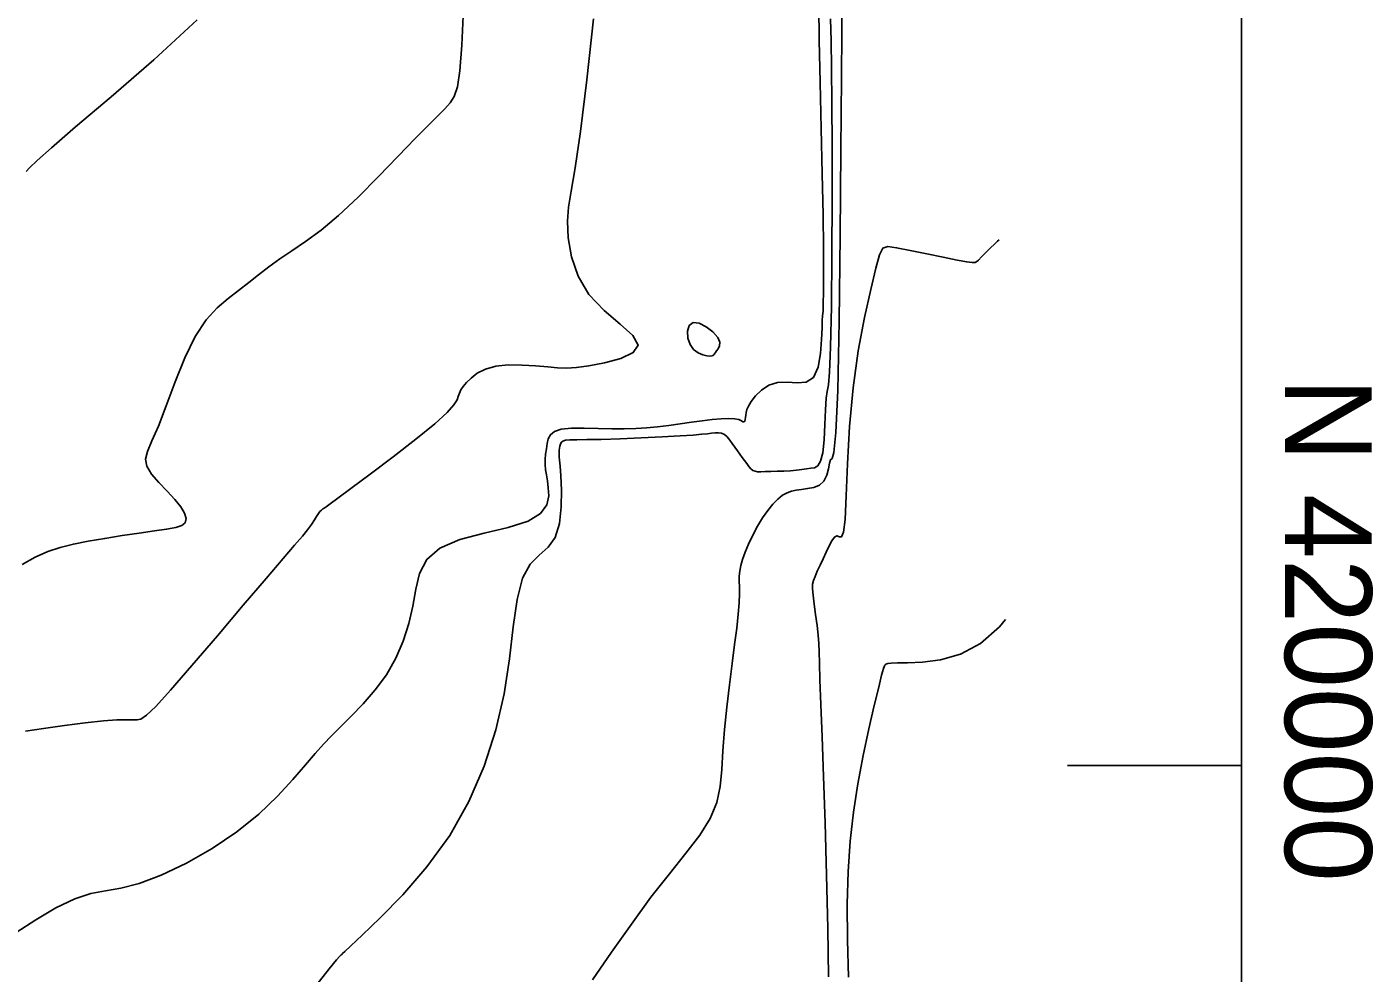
# Model space of a CAD drawing. Extents: x 2566142 to 2571431, y 418755 to 421584.
# Drawn here: x 2571198.2 to 2571430.5, y 419964.2 to 420127.5 of the extents above; entities that cross this region are included whole.
import ezdxf

# ---------------------------------------------------------------- set-up
doc = ezdxf.new("R2010")
doc.units = 0
for name, color, linetype in [('Contour_ADS_Major', 7, 'Continuous'), ('Contour_ADS_Minor', 7, 'Continuous'), ('Contour_ADS_State_Plane_Border', 7, 'Continuous')]:
    doc.layers.add(name, color=color, linetype=linetype)

msp = doc.modelspace()

# ---------------------------------------------------------------- linework, layer by layer
at = {"layer": 'Contour_ADS_Major'}
for points in [[(2571335.54, 420077.62), (2571335.6, 420078.43), (2571335.65, 420079.68), (2571335.69, 420081.8), (2571335.7, 420084.96), (2571335.68, 420089.33), (2571335.6, 420095.06), (2571335.46, 420102.13), (2571335.28, 420109.99), (2571335.1, 420117.92), (2571334.95, 420125.2), (2571334.86, 420131.28)], [(2571196.36, 419971.19), (2571199.72, 419973.37), (2571203.21, 419975.42), (2571206.47, 419977.01), (2571209.25, 419977.91), (2571211.78, 419978.4), (2571214.43, 419978.86), (2571217.56, 419979.66), (2571221.4, 419981.1), (2571225.73, 419983.14), (2571230.2, 419985.66), (2571234.46, 419988.54), (2571238.22, 419991.62), (2571241.43, 419994.72), (2571244.1, 419997.62), (2571246.27, 420000.13), (2571247.98, 420002.1), (2571249.4, 420003.69), (2571250.78, 420005.14), (2571252.32, 420006.69), (2571254.18, 420008.53), (2571256.25, 420010.66), (2571258.33, 420013.06), (2571260.25, 420015.69), (2571261.85, 420018.53), (2571263.13, 420021.5), (2571264.1, 420024.53), (2571264.79, 420027.54), (2571265.3, 420030.47), (2571265.96, 420033.18), (2571267.21, 420035.58), (2571269.45, 420037.54), (2571272.93, 420039), (2571277.11, 420040.12), (2571281.28, 420041.11), (2571284.71, 420042.19), (2571286.87, 420043.53), (2571287.94, 420045.02), (2571288.26, 420046.55), (2571288.19, 420047.96), (2571288.03, 420049.15), (2571287.86, 420050.16), (2571287.72, 420051.07), (2571287.64, 420051.95), (2571287.65, 420052.86), (2571287.72, 420053.78), (2571287.85, 420054.7), (2571288, 420055.58), (2571288.19, 420056.39), (2571288.55, 420057.1), (2571289.24, 420057.67), (2571290.42, 420058.05), (2571292.2, 420058.23), (2571294.4, 420058.25), (2571296.8, 420058.2), (2571299.16, 420058.14), (2571301.31, 420058.13), (2571303.27, 420058.17), (2571305.15, 420058.29), (2571307.03, 420058.46), (2571308.97, 420058.7), (2571310.94, 420058.98), (2571312.88, 420059.26), (2571314.74, 420059.52), (2571316.46, 420059.73), (2571318, 420059.87), (2571319.31, 420059.92), (2571320.33, 420059.87), (2571321.05, 420059.71), (2571321.51, 420059.52), (2571321.79, 420059.36), (2571321.96, 420059.31), (2571322.08, 420059.44), (2571322.17, 420059.72), (2571322.23, 420060.09), (2571322.28, 420060.51), (2571322.33, 420060.95), (2571322.45, 420061.45), (2571322.72, 420062.06), (2571323.2, 420062.84), (2571323.95, 420063.81), (2571324.98, 420064.81), (2571326.25, 420065.65), (2571327.75, 420066.13), (2571329.44, 420066.16), (2571331.15, 420066.04), (2571332.72, 420066.19), (2571333.96, 420067.01), (2571334.76, 420068.77), (2571335.18, 420071.11), (2571335.36, 420073.53), (2571335.43, 420075.55), (2571335.48, 420076.81), (2571335.54, 420077.62)]]:
    msp.add_lwpolyline(points, dxfattribs=at)
at = {"layer": 'Contour_ADS_Minor'}
for points in [[(2571273.29, 420124.34), (2571273.57, 420130.68)], [(2571318.11, 419999.33), (2571318.31, 420002.57), (2571318.62, 420006.21), (2571319.02, 420010.07), (2571319.48, 420013.95), (2571319.94, 420017.62), (2571320.35, 420020.9), (2571320.71, 420023.74), (2571320.98, 420026.14), (2571321.14, 420028.1), (2571321.2, 420029.64), (2571321.19, 420030.84), (2571321.15, 420031.82), (2571321.15, 420032.7), (2571321.23, 420033.58), (2571321.4, 420034.53), (2571321.71, 420035.59), (2571322.15, 420036.82), (2571322.76, 420038.24), (2571323.49, 420039.78), (2571324.31, 420041.33), (2571325.18, 420042.78), (2571326.06, 420044.05), (2571326.94, 420045.13), (2571327.79, 420046), (2571328.61, 420046.65), (2571329.39, 420047.1), (2571330.17, 420047.39), (2571330.99, 420047.56), (2571331.9, 420047.68), (2571332.93, 420047.8), (2571333.99, 420048), (2571334.97, 420048.4), (2571335.74, 420049.09), (2571336.24, 420050.1), (2571336.54, 420051.23), (2571336.72, 420052.22), (2571336.91, 420052.8), (2571337.17, 420053.01), (2571337.49, 420054.06), (2571337.83, 420057.47), (2571338.14, 420064.74), (2571338.38, 420076.7), (2571338.56, 420091.43), (2571338.69, 420106.3), (2571338.78, 420118.69), (2571338.83, 420126.64), (2571338.85, 420130.76)], [(2571198.07, 420102.54), (2571198.68, 420103.2), (2571199.95, 420104.43), (2571202.42, 420106.64), (2571206.6, 420110.24), (2571212.75, 420115.46), (2571220.1, 420121.84), (2571227.61, 420128.72)], [(2571291.5, 420093.96), (2571291.69, 420096.41), (2571292.13, 420099.17), (2571292.83, 420103.19), (2571293.74, 420109.43), (2571294.84, 420118.39), (2571295.99, 420128.9)], [(2571315.67, 420057.29), (2571316.37, 420057.38), (2571316.99, 420057.45), (2571317.56, 420057.46), (2571318.09, 420057.37), (2571318.59, 420057.13), (2571319.06, 420056.72), (2571319.52, 420056.19), (2571319.95, 420055.58), (2571320.39, 420054.94), (2571320.82, 420054.33), (2571321.25, 420053.74), (2571321.66, 420053.18), (2571322.06, 420052.64), (2571322.44, 420052.12), (2571322.81, 420051.65), (2571323.16, 420051.25), (2571323.51, 420050.96), (2571323.88, 420050.79), (2571324.31, 420050.72), (2571324.87, 420050.72), (2571325.61, 420050.74), (2571326.57, 420050.76), (2571327.69, 420050.79), (2571328.86, 420050.83), (2571330, 420050.89), (2571331.03, 420050.98), (2571331.94, 420051.09), (2571332.76, 420051.2), (2571333.49, 420051.31), (2571334.15, 420051.42), (2571334.72, 420051.75), (2571335.19, 420052.52), (2571335.55, 420053.97), (2571335.78, 420056.2), (2571335.93, 420058.85), (2571336.04, 420061.43), (2571336.16, 420063.42), (2571336.32, 420064.59), (2571336.52, 420065.75), (2571336.71, 420067.93), (2571336.89, 420072.21), (2571337.04, 420079.25), (2571337.13, 420088.2), (2571337.18, 420097.82), (2571337.19, 420106.87), (2571337.14, 420114.39), (2571337.07, 420120.38), (2571336.98, 420125.13), (2571336.91, 420128.91)], [(2571197.39, 420034.7), (2571199.64, 420035.96), (2571201.8, 420036.93), (2571203.95, 420037.66), (2571206.22, 420038.23), (2571208.76, 420038.73), (2571211.63, 420039.22), (2571214.65, 420039.7), (2571217.59, 420040.13), (2571220.2, 420040.5), (2571222.31, 420040.79), (2571223.88, 420041.07), (2571224.95, 420041.42), (2571225.54, 420041.92), (2571225.69, 420042.62), (2571225.42, 420043.54), (2571224.75, 420044.65), (2571223.72, 420045.93), (2571222.39, 420047.36), (2571220.98, 420048.85), (2571219.72, 420050.32), (2571218.89, 420051.67), (2571218.66, 420052.89), (2571219, 420054.24), (2571219.78, 420056.03), (2571220.89, 420058.59), (2571222.24, 420062.12), (2571223.78, 420066.22), (2571225.47, 420070.39), (2571227.26, 420074.08), (2571229.13, 420076.92), (2571231.03, 420079.01), (2571232.92, 420080.63), (2571234.74, 420082.01), (2571236.48, 420083.36), (2571238.2, 420084.72), (2571239.96, 420086.1), (2571241.86, 420087.47), (2571243.95, 420088.87), (2571246.31, 420090.45), (2571248.97, 420092.41), (2571252, 420094.94), (2571255.39, 420098.14), (2571258.91, 420101.68), (2571262.27, 420105.18), (2571265.19, 420108.22), (2571267.45, 420110.5), (2571269.12, 420112.14), (2571270.34, 420113.36), (2571271.24, 420114.38), (2571271.94, 420115.48), (2571272.5, 420117.15), (2571272.94, 420119.92), (2571273.29, 420124.34)], [(2571197.98, 420005.96), (2571201.08, 420006.4), (2571204.67, 420006.9), (2571208.28, 420007.36), (2571211.43, 420007.71), (2571213.75, 420007.87), (2571215.35, 420007.9), (2571216.42, 420007.87), (2571217.19, 420007.88), (2571217.89, 420008.03), (2571218.86, 420008.69), (2571220.44, 420010.21), (2571222.98, 420013.01), (2571226.68, 420017.26), (2571231.07, 420022.4), (2571235.55, 420027.67), (2571239.48, 420032.3), (2571242.41, 420035.72), (2571244.41, 420038.05), (2571245.75, 420039.61), (2571246.64, 420040.71), (2571247.31, 420041.62), (2571247.82, 420042.39), (2571248.21, 420043.02), (2571248.52, 420043.5), (2571248.78, 420043.85), (2571249.02, 420044.1), (2571249.26, 420044.29), (2571249.52, 420044.46), (2571249.86, 420044.69), (2571250.54, 420045.17), (2571251.85, 420046.13), (2571254.11, 420047.8), (2571257.46, 420050.3), (2571261.41, 420053.3), (2571265.33, 420056.35), (2571268.6, 420059.01), (2571270.73, 420060.94), (2571271.9, 420062.25), (2571272.44, 420063.11), (2571272.66, 420063.73), (2571272.85, 420064.28), (2571273.11, 420064.83), (2571273.49, 420065.42), (2571274.06, 420066.11), (2571274.85, 420066.9), (2571275.93, 420067.71), (2571277.34, 420068.43), (2571279.12, 420068.93), (2571281.28, 420069.15), (2571283.65, 420069.13), (2571286, 420068.98), (2571288.09, 420068.8), (2571289.8, 420068.66), (2571291.35, 420068.62), (2571293.03, 420068.73), (2571295.17, 420069.01), (2571297.89, 420069.52), (2571300.69, 420070.27), (2571302.85, 420071.28), (2571303.7, 420072.59), (2571302.78, 420074.22), (2571300.58, 420076.19), (2571297.81, 420078.55), (2571295.2, 420081.32), (2571293.33, 420084.49), (2571292.18, 420087.83), (2571291.63, 420091.08), (2571291.5, 420093.96)], [(2571338.42, 420039.51), (2571338.8, 420039.5), (2571339.14, 420040.27), (2571339.41, 420042.48), (2571339.61, 420046.56), (2571339.84, 420052.11), (2571340.19, 420058.52), (2571340.79, 420065.19), (2571341.69, 420071.57), (2571342.76, 420077.33), (2571343.84, 420082.18), (2571344.72, 420085.85), (2571345.34, 420088.15), (2571345.92, 420089.3), (2571346.8, 420089.6), (2571348.31, 420089.38), (2571350.65, 420088.91), (2571353.49, 420088.33), (2571356.35, 420087.74), (2571358.78, 420087.25), (2571360.41, 420086.94), (2571361.36, 420086.81), (2571361.86, 420086.84), (2571362.14, 420086.99), (2571362.42, 420087.27), (2571362.95, 420087.83), (2571363.97, 420088.86), (2571365.73, 420090.52), (2571366, 420090.77)], [(2571248.07, 419961.98), (2571250.39, 419964.93), (2571251.65, 419966.48), (2571252.2, 419967.1), (2571252.37, 419967.25), (2571252.46, 419967.31), (2571252.53, 419967.37), (2571252.57, 419967.41), (2571252.6, 419967.45), (2571252.68, 419967.53), (2571253.07, 419967.9), (2571254.1, 419968.87), (2571256.07, 419970.73), (2571259.18, 419973.71), (2571263.07, 419977.7), (2571267.23, 419982.5), (2571271.17, 419987.92), (2571274.48, 419993.77), (2571277.11, 419999.9), (2571279.12, 420006.15), (2571280.55, 420012.38), (2571281.49, 420018.4), (2571282.15, 420023.93), (2571282.81, 420028.69), (2571283.72, 420032.34), (2571285.04, 420034.75), (2571286.61, 420036.34), (2571288.15, 420037.69), (2571289.38, 420039.37), (2571290.12, 420041.79), (2571290.42, 420044.66), (2571290.46, 420047.55), (2571290.35, 420050.01), (2571290.24, 420051.69), (2571290.15, 420052.72), (2571290.09, 420053.31), (2571290.05, 420053.7), (2571290.06, 420054.06), (2571290.09, 420054.44), (2571290.14, 420054.81), (2571290.2, 420055.16), (2571290.27, 420055.49), (2571290.42, 420055.78), (2571290.7, 420056), (2571291.17, 420056.16), (2571291.93, 420056.23), (2571293.1, 420056.25), (2571294.85, 420056.27), (2571297.32, 420056.31), (2571300.57, 420056.41), (2571304.23, 420056.55), (2571307.85, 420056.72), (2571310.95, 420056.89), (2571313.19, 420057.04), (2571314.69, 420057.18), (2571315.67, 420057.29)], [(2571336.57, 419963.52), (2571336.44, 419971.93), (2571336.23, 419981.1), (2571335.98, 419990.1), (2571335.71, 419998.12), (2571335.45, 420004.96), (2571335.22, 420010.54), (2571335.05, 420014.77), (2571334.97, 420017.68), (2571334.93, 420019.63), (2571334.89, 420021.08), (2571334.78, 420022.48), (2571334.58, 420024.17), (2571334.33, 420026.05), (2571334.08, 420027.87), (2571333.88, 420029.42), (2571333.79, 420030.52), (2571333.81, 420031.3), (2571333.95, 420031.95), (2571334.22, 420032.64), (2571334.62, 420033.53), (2571335.11, 420034.57), (2571335.64, 420035.7), (2571336.17, 420036.84), (2571336.67, 420037.91), (2571337.14, 420038.81), (2571337.58, 420039.43), (2571338, 420039.66), (2571338.42, 420039.51)], [(2571339.99, 419963.47), (2571339.82, 419969.9), (2571339.79, 419976.05), (2571339.95, 419981.71), (2571340.31, 419986.96), (2571340.86, 419991.95), (2571341.6, 419996.84), (2571342.52, 420001.71), (2571343.51, 420006.32), (2571344.44, 420010.36), (2571345.21, 420013.53), (2571345.72, 420015.6), (2571346.03, 420016.76), (2571346.25, 420017.31), (2571346.46, 420017.51), (2571346.78, 420017.62), (2571347.38, 420017.68), (2571348.46, 420017.73), (2571350.21, 420017.76), (2571352.75, 420017.86), (2571355.88, 420018.24), (2571359.33, 420019.22), (2571362.8, 420021.06), (2571366.08, 420023.95), (2571367.11, 420025.19)], [(2571295.8, 419963.02), (2571299.12, 419967.77), (2571302.54, 419972.65), (2571305.91, 419977.27), (2571309.09, 419981.32), (2571311.95, 419984.85), (2571314.35, 419987.98), (2571316.14, 419990.86), (2571317.25, 419993.62), (2571317.83, 419996.39), (2571318.11, 419999.33)]]:
    msp.add_lwpolyline(points, dxfattribs=at)
msp.add_lwpolyline([(2571316.77, 420070.93), (2571316.85, 420071.04), (2571316.93, 420071.16), (2571317.05, 420071.33), (2571317.24, 420071.58), (2571317.52, 420071.95), (2571317.76, 420072.46), (2571317.78, 420073.11), (2571317.42, 420073.92), (2571316.58, 420074.85), (2571315.43, 420075.74), (2571314.22, 420076.35), (2571313.18, 420076.46), (2571312.52, 420075.94), (2571312.23, 420074.96), (2571312.29, 420073.79), (2571312.65, 420072.67), (2571313.27, 420071.82), (2571314.04, 420071.24), (2571314.84, 420070.89), (2571315.55, 420070.71), (2571316.07, 420070.66), (2571316.42, 420070.71), (2571316.64, 420070.81), (2571316.77, 420070.93)], close=True, dxfattribs=at)
at = {"layer": 'Contour_ADS_State_Plane_Border'}
msp.add_line((2571377.81, 420000), (2571407.81, 420000), dxfattribs=at)
msp.add_lwpolyline([(2566164.43, 418777.5), (2571407.81, 418777.5), (2571407.81, 421561.67), (2566164.43, 421561.67), (2566164.43, 418777.5)], close=True, dxfattribs=at)

# ---------------------------------------------------------------- texts
msp.add_text(' N 420000', height=15, rotation=270, dxfattribs=at).set_placement((2571415.31, 420072.5))

doc.saveas('drawing.dxf')
